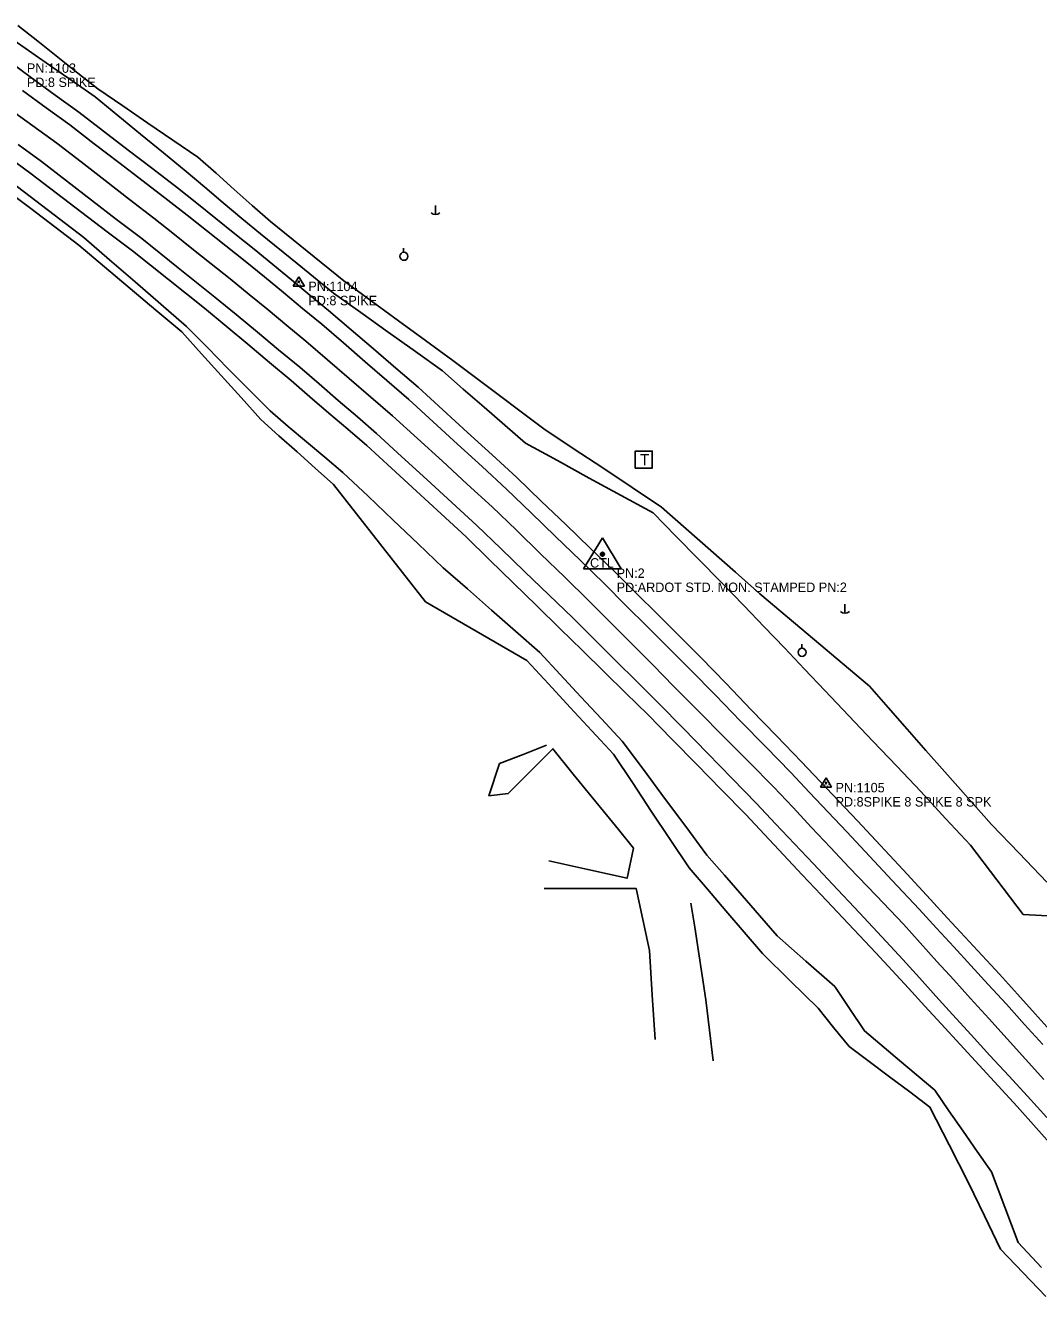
# Model space of a CAD drawing. Extents: x 1193883 to 1197064, y 1474583 to 1477379.
# Drawn here: x 1194735 to 1195271, y 1476233 to 1476906 of the extents above; entities that cross this region are included whole.
import ezdxf

# ---------------------------------------------------------------- set-up
doc = ezdxf.new("R2010")
doc.units = 0
for name, color, linetype in [('S_DITCHLINE', 7, 'Continuous'), ('S_EDGE_PAVEMENT', 7, 'Continuous'), ('S_PAVEMENT_CROWN', 7, 'Continuous'), ('S_PRIMARY_CTL', 7, 'Continuous'), ('S_PRIMARY_CTL_ANNOT', 7, 'Continuous'), ('S_SECONDARY_CTL', 7, 'Continuous'), ('S_SECONDARY_CTL_ANNOT', 7, 'Continuous'), ('S_SHOULDER', 7, 'Continuous'), ('S_TELEPHONE_UTILITIES', 7, 'Continuous'), ('S_UTILITY_POLE', 7, 'Continuous')]:
    doc.layers.add(name, color=color, linetype=linetype)

msp = doc.modelspace()

# ---------------------------------------------------------------- linework, layer by layer
at = {"layer": 'S_DITCHLINE'}
for points in [[(1194730.58, 1476905.74), (1194741.15, 1476897.33), (1194751.73, 1476888.92), (1194762.3, 1476880.51), (1194772.87, 1476872.1), (1194786.11, 1476863.09), (1194799.35, 1476854.08), (1194812.59, 1476845.06), (1194825.83, 1476836.05), (1194835.43, 1476827.5), (1194845.03, 1476818.95), (1194854.63, 1476810.41), (1194864.24, 1476801.86), (1194883.66, 1476786.16), (1194903.09, 1476770.46), (1194917.5, 1476759.95), (1194931.91, 1476749.44), (1194946.32, 1476738.93), (1194960.74, 1476728.42), (1194972.77, 1476719.36), (1194984.81, 1476710.3), (1194996.85, 1476701.25), (1195008.89, 1476692.19), (1195024.48, 1476681.83), (1195040.07, 1476671.46), (1195055.66, 1476661.1), (1195071.26, 1476650.74), (1195084.26, 1476639.27), (1195097.26, 1476627.79), (1195110.26, 1476616.32), (1195123.26, 1476604.85), (1195137.74, 1476592.63), (1195152.22, 1476580.42), (1195166.7, 1476568.2), (1195181.18, 1476555.98), (1195191.15, 1476544.63), (1195201.13, 1476533.27), (1195211.1, 1476521.92), (1195221.08, 1476510.56), (1195233.49, 1476496.67), (1195245.9, 1476482.79), (1195260.5, 1476467.51), (1195275.09, 1476452.23)], [(1194726.79, 1476898.95), (1194737.95, 1476891.21), (1194749.11, 1476883.47), (1194760.27, 1476875.73), (1194771.43, 1476867.99), (1194783.48, 1476858.1), (1194795.53, 1476848.2), (1194807.59, 1476838.31), (1194819.64, 1476828.41), (1194829.46, 1476820.14), (1194839.28, 1476811.87), (1194849.1, 1476803.6), (1194858.92, 1476795.33), (1194878.28, 1476779.68), (1194897.65, 1476764.04), (1194912.07, 1476753.73), (1194926.48, 1476743.43), (1194940.9, 1476733.13), (1194955.32, 1476722.82), (1194966.29, 1476713.26), (1194977.25, 1476703.71), (1194988.22, 1476694.15), (1194999.19, 1476684.59), (1195016.06, 1476675.36), (1195032.94, 1476666.13), (1195049.81, 1476656.91), (1195066.68, 1476647.68), (1195078.72, 1476635.44), (1195090.75, 1476623.2), (1195102.79, 1476610.96), (1195114.83, 1476598.72), (1195125.53, 1476587.45), (1195136.23, 1476576.18), (1195146.93, 1476564.92), (1195157.63, 1476553.65), (1195170.35, 1476540.29), (1195183.06, 1476526.93), (1195195.78, 1476513.57), (1195208.5, 1476500.21), (1195221.56, 1476485.97), (1195234.62, 1476471.72), (1195248.64, 1476453.38), (1195262.66, 1476435.05), (1195281.99, 1476433.98)], [(1194727.37, 1476822.52), (1194740.1, 1476812.85), (1194752.82, 1476803.17), (1194765.55, 1476793.49), (1194779.13, 1476781.73), (1194792.7, 1476769.97), (1194806.28, 1476758.21), (1194819.86, 1476746.45), (1194830.89, 1476735.25), (1194841.92, 1476724.04), (1194852.96, 1476712.84), (1194863.99, 1476701.64), (1194873.64, 1476693.5), (1194883.29, 1476685.37), (1194892.94, 1476677.24), (1194902.59, 1476669.11), (1194915.87, 1476656.5), (1194929.15, 1476643.9), (1194942.42, 1476631.29), (1194955.7, 1476618.69), (1194968.45, 1476607.47), (1194981.2, 1476596.25), (1194993.95, 1476585.03), (1195006.7, 1476573.81), (1195017.62, 1476562.08), (1195028.55, 1476550.35), (1195039.47, 1476538.62), (1195050.39, 1476526.88), (1195061.59, 1476511.81), (1195072.8, 1476496.74), (1195084.01, 1476481.66), (1195095.21, 1476466.59), (1195104.51, 1476455.89), (1195113.81, 1476445.19), (1195123.1, 1476434.49), (1195132.4, 1476423.79)], [(1194724.64, 1476818.44), (1194737.35, 1476808.74), (1194750.07, 1476799.04), (1194762.78, 1476789.33), (1194776.4, 1476777.88), (1194790.02, 1476766.43), (1194803.65, 1476754.98), (1194817.27, 1476743.53), (1194827.73, 1476731.94), (1194838.19, 1476720.35), (1194848.65, 1476708.77), (1194859.12, 1476697.18), (1194868.72, 1476688.57), (1194878.33, 1476679.95), (1194887.93, 1476671.34), (1194897.53, 1476662.73), (1194909.72, 1476647.18), (1194921.91, 1476631.63), (1194934.1, 1476616.09), (1194946.29, 1476600.54), (1194959.7, 1476592.79), (1194973.11, 1476585.05), (1194986.52, 1476577.3), (1194999.93, 1476569.56), (1195011.38, 1476557.15), (1195022.83, 1476544.75), (1195034.28, 1476532.35), (1195045.73, 1476519.94), (1195055.75, 1476504.9), (1195065.78, 1476489.86), (1195075.81, 1476474.83), (1195085.84, 1476459.79), (1195095.53, 1476448.44), (1195105.23, 1476437.09), (1195114.92, 1476425.75), (1195124.62, 1476414.4)], [(1195011.51, 1476463.48), (1195032.21, 1476458.89), (1195052.92, 1476454.31), (1195056.32, 1476470.28), (1195048.36, 1476480.06), (1195040.4, 1476489.84), (1195032.44, 1476499.62), (1195024.48, 1476509.4), (1195013.69, 1476522.82), (1195001.88, 1476510.96), (1194990.07, 1476499.11), (1194979.83, 1476497.95), (1194985.49, 1476514.95), (1194997.94, 1476519.83), (1195010.4, 1476524.72)], [(1195009.15, 1476448.82), (1195033.42, 1476448.85), (1195057.69, 1476448.87), (1195061.21, 1476432.46), (1195064.74, 1476416.05), (1195066.27, 1476392.46), (1195067.8, 1476368.87)], [(1195098.44, 1476357.71), (1195096.54, 1476373.84), (1195094.64, 1476389.98), (1195092.67, 1476402.77), (1195090.7, 1476415.57), (1195088.73, 1476428.36), (1195086.76, 1476441.16)], [(1195132.4, 1476423.79), (1195147.61, 1476410.42), (1195162.82, 1476397.05)], [(1195124.62, 1476414.4), (1195139.32, 1476399.94), (1195154.02, 1476385.49)], [(1195162.82, 1476397.05), (1195170.67, 1476385.27), (1195178.52, 1476373.5), (1195197.13, 1476357.76), (1195215.75, 1476342.03), (1195223.26, 1476331.24), (1195230.77, 1476320.45), (1195238.28, 1476309.66), (1195245.79, 1476298.87), (1195252.89, 1476280.14), (1195260, 1476261.4), (1195272.2, 1476248.23)], [(1195154.02, 1476385.49), (1195162.21, 1476375.37), (1195170.41, 1476365.26), (1195181.11, 1476357.23), (1195191.81, 1476349.19), (1195202.51, 1476341.16), (1195213.21, 1476333.13), (1195223.45, 1476313.09), (1195233.69, 1476293.06), (1195242.14, 1476275.52), (1195250.58, 1476257.98), (1195262.61, 1476245.42), (1195274.64, 1476232.85)]]:
    msp.add_lwpolyline(points, dxfattribs=at)
at = {"layer": 'S_EDGE_PAVEMENT'}
for points in [[(1194733.08, 1476871.25), (1194745.56, 1476862.15), (1194758.03, 1476853.04), (1194771.01, 1476843.11), (1194783.98, 1476833.17), (1194796.95, 1476823.24), (1194809.92, 1476813.31), (1194820.17, 1476805.22), (1194830.42, 1476797.14), (1194840.66, 1476789.06), (1194850.91, 1476780.97), (1194861.01, 1476772.63), (1194871.12, 1476764.29), (1194881.23, 1476755.95), (1194891.33, 1476747.61), (1194902.85, 1476737.66), (1194914.37, 1476727.71), (1194925.88, 1476717.75), (1194937.4, 1476707.8), (1194950.34, 1476695.93), (1194963.28, 1476684.06), (1194976.22, 1476672.19), (1194989.17, 1476660.32), (1195002.13, 1476647.75), (1195015.1, 1476635.19), (1195028.07, 1476622.62), (1195041.03, 1476610.06), (1195052.36, 1476598.75), (1195063.69, 1476587.43), (1195075.02, 1476576.12), (1195086.34, 1476564.81), (1195099.67, 1476551.16), (1195113, 1476537.51), (1195126.33, 1476523.86), (1195139.66, 1476510.21), (1195149.5, 1476499.76), (1195159.35, 1476489.31), (1195169.19, 1476478.86), (1195179.04, 1476468.41), (1195193.31, 1476453.14), (1195207.58, 1476437.88), (1195216.69, 1476427.94), (1195225.8, 1476418.01), (1195234.92, 1476408.07), (1195244.03, 1476398.13), (1195253.68, 1476387.55), (1195263.34, 1476376.96), (1195273, 1476366.37)], [(1194730.76, 1476842.7), (1194743.09, 1476833.65), (1194756.33, 1476823.46), (1194769.58, 1476813.27), (1194782.82, 1476803.08), (1194796.07, 1476792.9), (1194815.45, 1476777.42), (1194834.82, 1476761.95), (1194846.07, 1476752.67), (1194857.32, 1476743.39), (1194868.57, 1476734.1), (1194879.82, 1476724.82), (1194889.96, 1476716.05), (1194900.09, 1476707.27), (1194910.22, 1476698.5), (1194920.36, 1476689.73), (1194933.63, 1476677.55), (1194946.9, 1476665.37), (1194960.17, 1476653.19), (1194973.44, 1476641.01), (1194986.13, 1476628.79), (1194998.83, 1476616.57), (1195011.52, 1476604.35), (1195024.22, 1476592.13), (1195035.57, 1476580.86), (1195046.91, 1476569.59), (1195058.25, 1476558.33), (1195069.6, 1476547.06), (1195082.57, 1476533.75), (1195095.54, 1476520.43), (1195108.51, 1476507.12), (1195121.48, 1476493.8), (1195131.52, 1476483.16), (1195141.57, 1476472.51), (1195151.61, 1476461.87), (1195161.65, 1476451.22), (1195175.9, 1476436.04), (1195190.15, 1476420.86), (1195198.89, 1476411.2), (1195207.63, 1476401.54), (1195216.37, 1476391.87), (1195225.11, 1476382.21), (1195235.06, 1476371.37), (1195245.01, 1476360.53), (1195254.95, 1476349.69), (1195264.9, 1476338.85), (1195275.09, 1476327.59)]]:
    msp.add_lwpolyline(points, dxfattribs=at)
at = {"layer": 'S_PAVEMENT_CROWN'}
msp.add_lwpolyline([(1194725.83, 1476861.7), (1194738.53, 1476852.53), (1194751.22, 1476843.36), (1194764.02, 1476833.46), (1194776.82, 1476823.57), (1194789.62, 1476813.67), (1194802.42, 1476803.78), (1194812.56, 1476795.72), (1194822.69, 1476787.67), (1194832.83, 1476779.61), (1194842.97, 1476771.56), (1194852.97, 1476763.33), (1194862.96, 1476755.1), (1194872.96, 1476746.86), (1194882.96, 1476738.63), (1194894.44, 1476728.76), (1194905.91, 1476718.89), (1194917.38, 1476709.01), (1194928.86, 1476699.14), (1194942.03, 1476687.09), (1194955.2, 1476675.03), (1194968.38, 1476662.97), (1194981.55, 1476650.92), (1194994.36, 1476638.48), (1195007.17, 1476626.05), (1195019.99, 1476613.61), (1195032.8, 1476601.17), (1195044.03, 1476589.85), (1195055.27, 1476578.53), (1195066.5, 1476567.2), (1195077.74, 1476555.88), (1195090.96, 1476542.54), (1195104.19, 1476529.2), (1195117.41, 1476515.87), (1195130.63, 1476502.53), (1195140.6, 1476491.88), (1195150.57, 1476481.23), (1195160.55, 1476470.58), (1195170.52, 1476459.94), (1195184.87, 1476444.92), (1195199.22, 1476429.9), (1195208.09, 1476420.1), (1195216.95, 1476410.29), (1195225.82, 1476400.49), (1195234.69, 1476390.69), (1195244.4, 1476379.97), (1195254.1, 1476369.25), (1195263.81, 1476358.54), (1195273.52, 1476347.82)], dxfattribs=at)
at = {"layer": 'S_PRIMARY_CTL'}
for p, q in [((1195039.93, 1476634.51), (1195029.9, 1476618)), ((1195039.93, 1476634.51), (1195049.76, 1476618)), ((1195029.9, 1476618), (1195049.76, 1476618))]:
    msp.add_line(p, q, dxfattribs=at)
for radius in [1.04, 0.609, 0.344]:
    msp.add_circle((1195039.93, 1476625.81), radius, dxfattribs=at)
at = {"layer": 'S_SECONDARY_CTL'}
for p, q in [((1194879.28, 1476772.71), (1194876.27, 1476767.75)), ((1194879.28, 1476772.71), (1194882.23, 1476767.75)), ((1194876.27, 1476767.75), (1194882.23, 1476767.75)), ((1195158.27, 1476507.38), (1195155.26, 1476502.43)), ((1195158.27, 1476507.38), (1195161.22, 1476502.43)), ((1195155.26, 1476502.43), (1195161.22, 1476502.43))]:
    msp.add_line(p, q, dxfattribs=at)
for centre, radius in [((1194879.28, 1476770.1), 0.311), ((1194879.28, 1476770.1), 0.183), ((1194879.28, 1476770.1), 0.103), ((1195158.27, 1476504.77), 0.311), ((1195158.27, 1476504.77), 0.183), ((1195158.27, 1476504.77), 0.103)]:
    msp.add_circle(centre, radius, dxfattribs=at)
at = {"layer": 'S_SHOULDER'}
for points in [[(1194725.34, 1476887.21), (1194737.84, 1476878.06), (1194750.34, 1476868.9), (1194762.84, 1476859.75), (1194775.9, 1476849.74), (1194788.96, 1476839.74), (1194802.02, 1476829.74), (1194815.08, 1476819.73), (1194825.2, 1476811.62), (1194835.32, 1476803.5), (1194845.45, 1476795.38), (1194855.57, 1476787.26), (1194865.43, 1476779.15), (1194875.29, 1476771.03), (1194885.15, 1476762.91), (1194895.02, 1476754.79), (1194906.88, 1476744.64), (1194918.75, 1476734.49), (1194930.61, 1476724.33), (1194942.48, 1476714.18), (1194955.5, 1476702.24), (1194968.52, 1476690.3), (1194981.54, 1476678.37), (1194994.55, 1476666.43), (1195007.51, 1476653.95), (1195020.47, 1476641.47), (1195033.43, 1476628.99), (1195046.39, 1476616.52), (1195057.8, 1476605.18), (1195069.22, 1476593.83), (1195080.64, 1476582.49), (1195092.06, 1476571.15), (1195105.38, 1476557.32), (1195118.7, 1476543.5), (1195132.02, 1476529.67), (1195145.34, 1476515.84), (1195155.17, 1476505.45), (1195165, 1476495.06), (1195174.83, 1476484.67), (1195184.66, 1476474.28), (1195199.06, 1476458.69), (1195213.46, 1476443.11), (1195222.6, 1476433.22), (1195231.73, 1476423.34), (1195240.87, 1476413.45), (1195250.01, 1476403.57), (1195259.51, 1476393.01), (1195269, 1476382.46), (1195278.5, 1476371.91)], [(1194725.49, 1476836.2), (1194737.57, 1476827.2), (1194750.98, 1476816.99), (1194764.39, 1476806.77), (1194777.8, 1476796.56), (1194791.21, 1476786.34), (1194810.26, 1476771.24), (1194829.31, 1476756.13), (1194840.76, 1476746.53), (1194852.21, 1476736.94), (1194863.65, 1476727.34), (1194875.1, 1476717.74), (1194885.14, 1476709.16), (1194895.17, 1476700.57), (1194905.21, 1476691.98), (1194915.25, 1476683.39), (1194928.37, 1476671.3), (1194941.49, 1476659.2), (1194954.61, 1476647.11), (1194967.73, 1476635.01), (1194980.19, 1476622.84), (1194992.66, 1476610.67), (1195005.13, 1476598.49), (1195017.59, 1476586.32), (1195029.17, 1476574.98), (1195040.75, 1476563.64), (1195052.33, 1476552.3), (1195063.92, 1476540.96), (1195076.87, 1476527.71), (1195089.82, 1476514.47), (1195102.77, 1476501.22), (1195115.72, 1476487.98), (1195125.7, 1476477.38), (1195135.68, 1476466.77), (1195145.66, 1476456.16), (1195155.64, 1476445.56), (1195170.14, 1476430.23), (1195184.64, 1476414.89), (1195193.27, 1476405.47), (1195201.9, 1476396.04), (1195210.53, 1476386.61), (1195219.16, 1476377.18), (1195229.2, 1476366.24), (1195239.24, 1476355.3), (1195249.28, 1476344.36), (1195259.32, 1476333.43), (1195269.41, 1476322.17), (1195279.49, 1476310.91)]]:
    msp.add_lwpolyline(points, dxfattribs=at)
at = {"layer": 'S_TELEPHONE_UTILITIES'}
msp.add_lwpolyline([(1195057.31, 1476671.41), (1195057.31, 1476680.41), (1195066.31, 1476680.41), (1195066.31, 1476671.41)], close=True, dxfattribs=at)
at = {"layer": 'S_UTILITY_POLE'}
for p, q in [((1194951.52, 1476810.39), (1194951.52, 1476805.66)), ((1194934.72, 1476785.66), (1194934.72, 1476787.77)), ((1195168.19, 1476599.31), (1195168.19, 1476594.58)), ((1195145.44, 1476576.01), (1195145.44, 1476578.12))]:
    msp.add_line(p, q, dxfattribs=at)
for centre in [(1194934.84, 1476783.52), (1195145.56, 1476573.87)]:
    msp.add_circle(centre, 2.13, dxfattribs=at)
for centre in [(1194951.58, 1476809.08), (1195168.25, 1476598.01)]:
    msp.add_arc(centre, 3.41, 226.39718, 313.60282, dxfattribs=at)

# ---------------------------------------------------------------- texts
at = {"layer": 'S_PRIMARY_CTL'}
msp.add_text('CTL', height=5, rotation=360, dxfattribs=at).set_placement((1195033.35, 1476618.73))
at = {"layer": 'S_PRIMARY_CTL_ANNOT'}
for s, p in [('PN:2', (1195047.43, 1476613.31)), ('PD:ARDOT STD. MON. STAMPED PN:2', (1195047.43, 1476605.81))]:
    msp.add_text(s, height=5, dxfattribs=at).set_placement(p)
at = {"layer": 'S_SECONDARY_CTL'}
for p in [(1194878.08, 1476768.08), (1195157.07, 1476502.76)]:
    msp.add_text('TV', height=1.5, rotation=360, dxfattribs=at).set_placement(p)
at = {"layer": 'S_SECONDARY_CTL_ANNOT'}
for s, p in [('PN:1103', (1194735.31, 1476880.65)), ('PD:8 SPIKE', (1194735.31, 1476873.15)), ('PN:1104', (1194884.28, 1476765.1)), ('PD:8 SPIKE', (1194884.28, 1476757.6)), ('PN:1105', (1195163.27, 1476499.77)), ('PD:8SPIKE 8 SPIKE 8 SPK', (1195163.27, 1476492.27))]:
    msp.add_text(s, height=5, dxfattribs=at).set_placement(p)
at = {"layer": 'S_TELEPHONE_UTILITIES'}
msp.add_text('T', height=6, rotation=360, dxfattribs=at).set_placement((1195059.87, 1476672.91))

doc.saveas('drawing.dxf')
